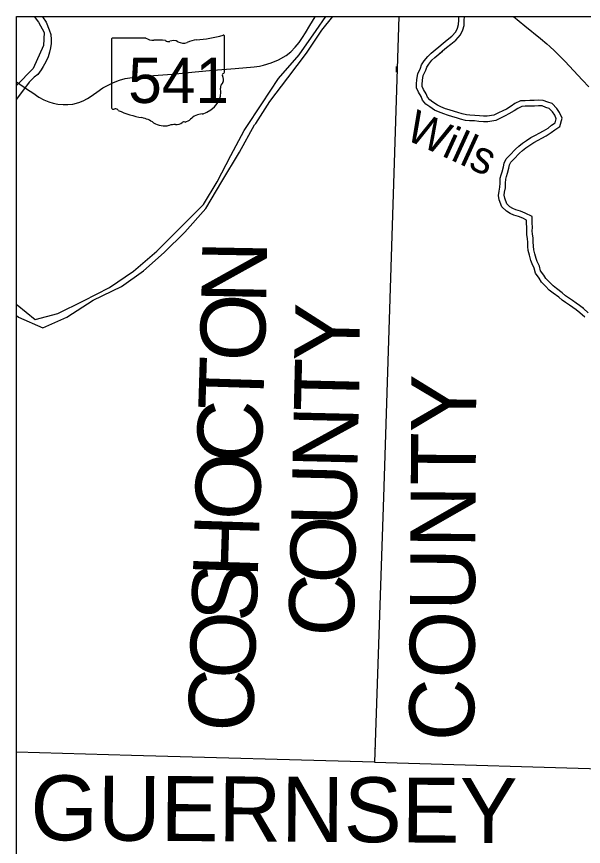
# Model space of a CAD drawing. Extents: x -29.6 to 34, y 0 to 22.
# Drawn here: x -29.583 to -28.032, y 10.939 to 13.208 of the extents above; entities that cross this region are included whole.
import ezdxf

# ---------------------------------------------------------------- set-up
doc = ezdxf.new("R2010")
doc.units = 0
for name, color, linetype in [('GM_X_County', 7, 'Continuous'), ('GM_X_County_Text', 7, 'Continuous'), ('GM_X_Major_River', 7, 'Continuous'), ('GM_X_Major_River_Text', 7, 'Continuous'), ('GM_X_Minor_Lake', 7, 'Continuous'), ('GM_X_Minor_River', 7, 'Continuous'), ('GM_X_State_Route', 7, 'Continuous'), ('GM_X_State_Shield', 7, 'Continuous'), ('GM_X_Township', 7, 'Continuous'), ('SH_Text', 7, 'Continuous')]:
    doc.layers.add(name, color=color, linetype=linetype)

msp = doc.modelspace()

# ---------------------------------------------------------------- linework, layer by layer
at = {"layer": 'GM_X_County'}
msp.add_lwpolyline([(-28.537, 13.2079), (-28.5794, 11.894), (-28.604, 11.1697), (-29.2686, 11.1872), (-29.5833, 11.1962)], dxfattribs=at)
at = {"layer": 'GM_X_Major_River'}
for points in [[(-29.5351, 13.2079), (-29.5236, 13.1929), (-29.5082, 13.1645), (-29.5099, 13.1286), (-29.5383, 13.0661), (-29.5833, 13.0192)], [(-29.5833, 12.3905), (-29.5783, 12.3857), (-29.5112, 12.3572), (-29.4462, 12.3858), (-29.3737, 12.4329), (-29.2959, 12.4696), (-29.2361, 12.5132), (-29.1798, 12.5632), (-29.1227, 12.6186), (-29.0653, 12.6831), (-29.0219, 12.7566), (-28.9736, 12.8372), (-28.9323, 12.9121), (-28.9288, 12.916), (-28.8905, 12.9756), (-28.8408, 13.0409), (-28.7901, 13.1076), (-28.7482, 13.1704), (-28.7176, 13.2079)], [(-29.5833, 12.4208), (-29.5813, 12.4195), (-29.5327, 12.3797), (-29.4706, 12.3963), (-29.3999, 12.431), (-29.3288, 12.467), (-29.263, 12.512), (-29.1999, 12.5662), (-29.0719, 12.6941), (-29.0343, 12.7563), (-28.997, 12.8277), (-28.9604, 12.8967), (-28.9572, 12.9023), (-28.9121, 12.9694), (-28.8667, 13.039), (-28.8103, 13.1031), (-28.7635, 13.1698), (-28.7369, 13.2079)], [(-29.5125, 13.2079), (-29.5122, 13.2074), (-29.502, 13.1931), (-29.494, 13.1714), (-29.4899, 13.159), (-29.4882, 13.1455), (-29.4886, 13.1342), (-29.4905, 13.1221), (-29.493, 13.1104), (-29.497, 13.098), (-29.5035, 13.0843), (-29.5106, 13.0715), (-29.5157, 13.062), (-29.5253, 13.0496), (-29.5356, 13.0423)], [(-28.4277, 13.1253), (-28.4164, 13.135), (-28.4049, 13.1447), (-28.3922, 13.1547), (-28.3813, 13.1665), (-28.3768, 13.1765), (-28.3741, 13.1861), (-28.3735, 13.1981), (-28.3728, 13.2079)], [(-28.4177, 13.1138), (-28.4066, 13.1234), (-28.3952, 13.1329), (-28.3818, 13.1435), (-28.3684, 13.158), (-28.3625, 13.1713), (-28.3589, 13.1836), (-28.3583, 13.1972), (-28.3575, 13.2079)], [(-28.4176, 13.1139), (-28.4066, 13.1234), (-28.3952, 13.1329), (-28.3818, 13.1435), (-28.3684, 13.158), (-28.3625, 13.1713), (-28.3589, 13.1836), (-28.3583, 13.1972), (-28.3575, 13.2079)], [(-28.0422, 12.3983), (-28.0518, 12.4057), (-28.0611, 12.4123), (-28.0707, 12.4193), (-28.0814, 12.426), (-28.0903, 12.4326), (-28.0996, 12.4404), (-28.1153, 12.4519), (-28.1257, 12.46), (-28.1364, 12.4712), (-28.1472, 12.4821), (-28.1536, 12.4923), (-28.1633, 12.5068), (-28.167, 12.5202), (-28.1724, 12.5323), (-28.1764, 12.5414), (-28.1801, 12.5553), (-28.1831, 12.568), (-28.1842, 12.579), (-28.1847, 12.5914), (-28.1852, 12.6006), (-28.1867, 12.612), (-28.1875, 12.6208), (-28.1869, 12.6318), (-28.1877, 12.6421), (-28.1878, 12.6517), (-28.1981, 12.6566), (-28.2098, 12.6614), (-28.2226, 12.6652), (-28.2326, 12.6697), (-28.2429, 12.6756), (-28.2551, 12.6876), (-28.2624, 12.707), (-28.265, 12.719), (-28.263, 12.7304), (-28.2606, 12.7418), (-28.2603, 12.7528), (-28.2598, 12.7659), (-28.257, 12.7748), (-28.255, 12.7837), (-28.2512, 12.7972), (-28.2492, 12.8072), (-28.2433, 12.8189), (-28.2334, 12.8286), (-28.218, 12.8454), (-28.2089, 12.8533), (-28.1994, 12.8616), (-28.1878, 12.8688), (-28.1762, 12.8771), (-28.1631, 12.8836), (-28.1533, 12.889), (-28.1416, 12.8955), (-28.129, 12.9031), (-28.1195, 12.911), (-28.1096, 12.9171), (-28.1065, 12.9288), (-28.1109, 12.938), (-28.1166, 12.9472), (-28.1259, 12.9567), (-28.1352, 12.9598), (-28.1455, 12.9636), (-28.1551, 12.9638), (-28.1664, 12.963), (-28.1791, 12.9629), (-28.1915, 12.9627), (-28.2007, 12.9623), (-28.2117, 12.9569), (-28.2215, 12.95), (-28.236, 12.9417), (-28.2462, 12.9367), (-28.2575, 12.9312), (-28.2723, 12.924), (-28.2942, 12.9202), (-28.3059, 12.9201), (-28.3183, 12.9211), (-28.3307, 12.9227), (-28.3442, 12.9233), (-28.3552, 12.9242), (-28.3683, 12.9276), (-28.3797, 12.9311), (-28.3897, 12.9338), (-28.4042, 12.9386), (-28.4145, 12.9417), (-28.4288, 12.9473), (-28.4394, 12.9525), (-28.4526, 12.9616), (-28.4633, 12.9685), (-28.4723, 12.9798), (-28.4763, 12.9897), (-28.4832, 13.0017), (-28.4889, 13.0133), (-28.489, 13.0229), (-28.4877, 13.0357), (-28.4858, 13.0517), (-28.4778, 13.067), (-28.475, 13.0759), (-28.4681, 13.0869), (-28.4583, 13.0991), (-28.4491, 13.1081), (-28.4375, 13.1167), (-28.4277, 13.1253)], [(-28.0325, 12.4101), (-28.0427, 12.4179), (-28.0522, 12.4247), (-28.0622, 12.432), (-28.0728, 12.4386), (-28.0809, 12.4446), (-28.0902, 12.4523), (-28.1061, 12.464), (-28.1154, 12.4713), (-28.1255, 12.4818), (-28.1351, 12.4916), (-28.1409, 12.5007), (-28.1493, 12.5132), (-28.1526, 12.5254), (-28.1585, 12.5384), (-28.162, 12.5465), (-28.1653, 12.5589), (-28.168, 12.5705), (-28.169, 12.5801), (-28.1695, 12.5921), (-28.17, 12.602), (-28.1715, 12.6137), (-28.1722, 12.6211), (-28.1716, 12.632), (-28.1724, 12.6428), (-28.1726, 12.6614), (-28.1919, 12.6705), (-28.2047, 12.6758), (-28.2173, 12.6795), (-28.2256, 12.6833), (-28.2336, 12.6878), (-28.242, 12.696), (-28.2477, 12.7113), (-28.2494, 12.7193), (-28.248, 12.7275), (-28.2454, 12.7401), (-28.2451, 12.7523), (-28.2446, 12.7633), (-28.2423, 12.7709), (-28.2402, 12.78), (-28.2364, 12.7937), (-28.2346, 12.8022), (-28.2308, 12.8099), (-28.2225, 12.8181), (-28.2074, 12.8345), (-28.1989, 12.8419), (-28.1903, 12.8493), (-28.1793, 12.8561), (-28.1683, 12.864), (-28.156, 12.8701), (-28.1459, 12.8757), (-28.134, 12.8823), (-28.1201, 12.8906), (-28.1105, 12.8986), (-28.0964, 12.9074), (-28.0904, 12.9303), (-28.0975, 12.9453), (-28.1046, 12.9567), (-28.1176, 12.9699), (-28.1301, 12.9741), (-28.1426, 12.9787), (-28.1554, 12.979), (-28.167, 12.9782), (-28.1793, 12.9781), (-28.192, 12.978), (-28.2047, 12.9773), (-28.2195, 12.97), (-28.2297, 12.9629), (-28.2432, 12.9552), (-28.2529, 12.9503), (-28.2642, 12.9449), (-28.277, 12.9386), (-28.2956, 12.9354), (-28.3054, 12.9353), (-28.3167, 12.9362), (-28.3294, 12.9379), (-28.3432, 12.9385), (-28.3526, 12.9393), (-28.3642, 12.9423), (-28.3755, 12.9457), (-28.3852, 12.9484), (-28.3996, 12.9531), (-28.4096, 12.9561), (-28.4226, 12.9612), (-28.4317, 12.9656), (-28.4441, 12.9742), (-28.4529, 12.9799), (-28.459, 12.9875), (-28.4625, 12.9963), (-28.4697, 13.0088), (-28.4737, 13.017), (-28.4738, 13.0222), (-28.4726, 13.034), (-28.471, 13.0471), (-28.4636, 13.0612), (-28.4611, 13.0695), (-28.4556, 13.0781), (-28.4469, 13.0889), (-28.4392, 13.0965), (-28.4279, 13.1048), (-28.4176, 13.1139)], [(-28.0329, 12.4104), (-28.0427, 12.4179), (-28.0522, 12.4247), (-28.0622, 12.432), (-28.0728, 12.4386), (-28.0809, 12.4446), (-28.0902, 12.4523), (-28.1061, 12.464), (-28.1154, 12.4713), (-28.1255, 12.4818), (-28.1351, 12.4916), (-28.1409, 12.5007), (-28.1493, 12.5132), (-28.1526, 12.5254), (-28.1585, 12.5384), (-28.162, 12.5465), (-28.1653, 12.5589), (-28.168, 12.5705), (-28.169, 12.5801), (-28.1695, 12.5921), (-28.17, 12.602), (-28.1715, 12.6137), (-28.1722, 12.6211), (-28.1716, 12.632), (-28.1724, 12.6428), (-28.1726, 12.6614), (-28.1919, 12.6705), (-28.2047, 12.6758), (-28.2173, 12.6795), (-28.2256, 12.6833), (-28.2336, 12.6878), (-28.242, 12.696), (-28.2477, 12.7113), (-28.2494, 12.7193), (-28.248, 12.7275), (-28.2454, 12.7401), (-28.2451, 12.7523), (-28.2446, 12.7633), (-28.2423, 12.7709), (-28.2402, 12.78), (-28.2364, 12.7937), (-28.2346, 12.8022), (-28.2308, 12.8099), (-28.2225, 12.8181), (-28.2074, 12.8345), (-28.1989, 12.8419), (-28.1903, 12.8493), (-28.1793, 12.8561), (-28.1683, 12.864), (-28.156, 12.8701), (-28.1459, 12.8757), (-28.134, 12.8823), (-28.1201, 12.8906), (-28.1105, 12.8986), (-28.0964, 12.9074), (-28.0904, 12.9303), (-28.0975, 12.9453), (-28.1046, 12.9567), (-28.1176, 12.9699), (-28.1301, 12.9741), (-28.1426, 12.9787), (-28.1554, 12.979), (-28.167, 12.9782), (-28.1793, 12.9781), (-28.192, 12.978), (-28.2047, 12.9773), (-28.2195, 12.97), (-28.2297, 12.9629), (-28.2432, 12.9552), (-28.2529, 12.9503), (-28.2642, 12.9449), (-28.277, 12.9386), (-28.2956, 12.9354), (-28.3054, 12.9353), (-28.3167, 12.9362), (-28.3294, 12.9379), (-28.3432, 12.9385), (-28.3526, 12.9393), (-28.3642, 12.9423), (-28.3755, 12.9457), (-28.3852, 12.9484), (-28.3996, 12.9531), (-28.4096, 12.9561), (-28.4226, 12.9612), (-28.4317, 12.9656), (-28.4441, 12.9742), (-28.4529, 12.9799), (-28.459, 12.9875), (-28.4625, 12.9963), (-28.4697, 13.0088), (-28.4737, 13.017), (-28.4738, 13.0222), (-28.4726, 13.034), (-28.471, 13.0471), (-28.4636, 13.0612), (-28.4611, 13.0695), (-28.4556, 13.0781), (-28.4469, 13.0889), (-28.4392, 13.0965), (-28.4279, 13.1048), (-28.4176, 13.1138)], [(-29.5356, 13.0423), (-29.5488, 13.0285), (-29.5833, 12.9817)], [(-28.0286, 12.3864), (-28.0422, 12.3983)], [(-28.0189, 12.3982), (-28.0325, 12.4101)]]:
    msp.add_lwpolyline(points, dxfattribs=at)
at = {"layer": 'GM_X_Minor_Lake'}
msp.add_line((-28.5439, 13.0557), (-28.5434, 13.0712), dxfattribs=at)
at = {"layer": 'GM_X_Minor_River'}
msp.add_lwpolyline([(-28.602, 11.2068), (-28.6019, 11.2061)], dxfattribs=at)
at = {"layer": 'GM_X_State_Route'}
for points in [[(-29.5833, 13.0296), (-29.5531, 13.009), (-29.5388, 12.9991), (-29.5224, 12.9878), (-29.5089, 12.9804), (-29.4951, 12.9747), (-29.4834, 12.9713), (-29.4702, 12.9686), (-29.4556, 12.9674), (-29.4429, 12.9674), (-29.4296, 12.9689), (-29.4125, 12.9733), (-29.4011, 12.9778), (-29.3894, 12.9837), (-29.3823, 12.9884), (-29.3634, 13.0016), (-29.3469, 13.0128), (-29.3328, 13.0204), (-29.3177, 13.0277), (-29.3021, 13.0337), (-29.2857, 13.0383), (-29.2735, 13.0405), (-29.2615, 13.0422), (-29.2087, 13.0468), (-29.1577, 13.0509), (-29.0945, 13.057), (-29.045, 13.0612), (-28.9849, 13.0658), (-28.9328, 13.0704), (-28.9185, 13.0723), (-28.9075, 13.0749), (-28.8864, 13.0812), (-28.8668, 13.09), (-28.8457, 13.1017), (-28.8333, 13.1117), (-28.8212, 13.1242), (-28.8098, 13.1375), (-28.8007, 13.1506), (-28.7927, 13.1636), (-28.7807, 13.1838), (-28.7667, 13.2072), (-28.7662, 13.2079)], [(-28.2236, 13.2079), (-28.1922, 13.1824), (-28.1498, 13.1477), (-28.1322, 13.1333), (-28.1238, 13.126), (-28.1111, 13.1141), (-28.1023, 13.1055), (-28.0942, 13.0973), (-28.0897, 13.0927), (-28.0833, 13.0859), (-28.0347, 13.034), (-28.0175, 13.0159)]]:
    msp.add_lwpolyline(points, dxfattribs=at)
at = {"layer": 'GM_X_State_Shield'}
for p, q in [((-29.3233, 13.1461), (-29.3233, 12.9585)), ((-29.2298, 13.1493), (-29.3202, 13.1493)), ((-29.0143, 13.0558), (-29.0143, 13.1539)), ((-29.0143, 13.0558), (-29.0143, 13.0558))]:
    msp.add_line(p, q, dxfattribs=at)
for centre, major_axis, start_param, end_param in [((-29.3198, 13.1465), (0.00358, 0), 1.712693, 3.28349), ((-29.2082, 13.1711), (0.0347, 0), 4.042523, 4.731795), ((-29.1967, 13.044), (0.1246, 0), 1.404758, 1.657858), ((-29.1684, 13.1474), (0.01, 0), 3.836095, 5.185415), ((-29.1537, 13.1258), (0.0208, 0), 0.950623, 2.079405), ((-29.1268, 13.1555), (0.0251, 0), 4.081561, 5.145723), ((-29.0826, 13.092), (0.0659, 0), 1.699011, 2.107814), ((-29.1244, 13.4051), (0.3277, 0), 4.814394, 5.042369), ((-29.0177, 13.1543), (0.00344, 0), 6.141152, 7.989035), ((-29.0151, 13.0486), (0.00532, 0), 1.883978, 3.671073), ((-29.018, 13.0554), (0.00368, 0), 5.05454, 6.418171), ((-29.002, 13.0147), (0.0232, 0), 2.387724, 3.262537), ((-29.049, 13.0362), (0.032, 0), 5.934695, 6.695948), ((-29.106, 13.0022), (0.082, 0), 5.101752, 6.440018), ((-29.3197, 12.958), (0.00361, 0), 3.00124, 4.508301), ((-29.3192, 12.9772), (0.0276, 0), 4.665946, 4.897461), ((-29.3135, 12.9476), (0.00994, 0), 0.519207, 1.627899), ((-29.1881, 13.1162), (0.2366, 0), 4.195997, 4.488961), ((-29.0715, 12.9058), (0.0449, 0), 1.647645, 2.488434), ((-29.2586, 12.8742), (0.074, 0), 0.823519, 1.323587), ((-29.1785, 12.9467), (0.047, 0), 4.026481, 4.996735), ((-29.1514, 12.8818), (0.0386, 0), 1.495662, 1.94098), ((-29.148, 12.9326), (0.025, 0), 4.691044, 5.507374), ((-29.1253, 12.9145), (0.00705, 0), 1.147584, 2.315152), ((-29.1283, 12.9403), (0.0265, 0), 4.937069, 5.64225)]:
    msp.add_ellipse(centre, major_axis=major_axis, ratio=0.8, start_param=start_param, end_param=end_param, dxfattribs=at)
at = {"layer": 'GM_X_Township'}
msp.add_lwpolyline([(-28.604, 11.1697), (-27.9229, 11.1492)], dxfattribs=at)
at = {"layer": 'SH_Text'}
msp.add_lwpolyline([(-29.5833, 13.2079), (-10.7478, 13.2079), (-10.7478, 1.0528), (-29.5833, 1.0528)], close=True, dxfattribs=at)

# ---------------------------------------------------------------- texts
at = {"layer": 'GM_X_County_Text'}
for s, height, rotation, p in [('N', 0.1776, 88.9622, (-28.9004, 12.4219)), ('O', 0.1776, 88.469, (-28.9046, 12.2635)), ('Y', 0.1776, 88.6358, (-28.6465, 12.2634)), ('T', 0.1776, 88.2126, (-28.9088, 12.1302)), ('T', 0.1776, 88.6358, (-28.6473, 12.126)), ('COUNTY', 0.17756, 89.6417, (-28.3315, 11.2264)), ('C', 0.1776, 88.1616, (-28.9134, 11.9853)), ('N', 0.1776, 88.6373, (-28.651, 11.9693)), ('O', 0.1776, 88.1583, (-28.9185, 11.8287)), ('U', 0.1776, 88.6368, (-28.6547, 11.8126)), ('H', 0.1776, 88.1594, (-28.9235, 11.672)), ('O', 0.1776, 88.6499, (-28.6584, 11.656)), ('S', 0.1776, 88.159, (-28.9274, 11.5514)), ('C', 0.1776, 88.7376, (-28.6616, 11.5113)), ('O', 0.1776, 88.1594, (-28.9324, 11.3948)), ('C', 0.1776, 88.1594, (-28.937, 11.2501)), ('GUERNSEY', 0.17756, 359.6417, (-29.5457, 10.9562))]:
    msp.add_text(s, height=height, rotation=rotation, dxfattribs=at).set_placement(p)
at = {"layer": 'GM_X_Major_River_Text'}
msp.add_text('Wills', height=0.08874, rotation=335.4321, dxfattribs=at).set_placement((-28.524, 12.8745))
at = {"layer": 'GM_X_State_Shield'}
msp.add_text('541', height=0.1236, dxfattribs=at).set_placement((-29.2778, 12.9717))

doc.saveas('drawing.dxf')
